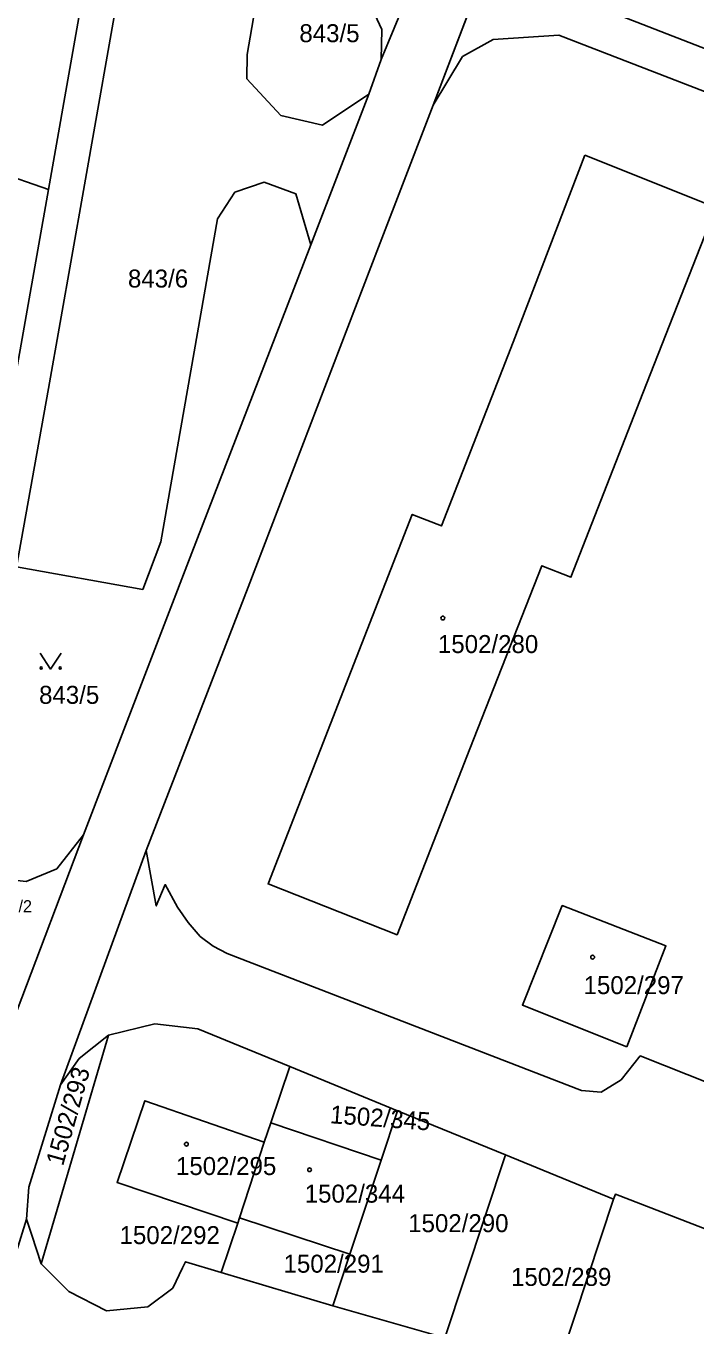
# Model space of a CAD drawing. Extents: x -737240 to -735272, y -1119606 to -1117878.
# Drawn here: x -736841.8 to -736778.5, y -1118698.3 to -1118575.4 of the extents above; entities that cross this region are included whole.
import ezdxf

# ---------------------------------------------------------------- set-up
doc = ezdxf.new("R2010")
doc.units = 0
for name, color, linetype in [('Level 1', 7, 'Continuous'), ('Level 13', 7, 'Continuous'), ('Level 16', 7, 'Continuous'), ('Level 18', 7, 'Continuous'), ('Level 19', 7, 'Continuous'), ('Level 25', 7, 'Continuous')]:
    doc.layers.add(name, color=color, linetype=linetype)

msp = doc.modelspace()

# ---------------------------------------------------------------- linework, layer by layer
at = {"layer": 'Level 1'}
for p, q in [((-736799.83, -1118558.11), (-736808.27, -1118578.61)), ((-736803.36, -1118582.92), (-736794.62, -1118560.04)), ((-736808.27, -1118578.61), (-736809.42, -1118581.87)), ((-736809.42, -1118581.87), (-736814.92, -1118596.1)), ((-736839.7, -1118590.89), (-736858.98, -1118584.15)), ((-736839.7, -1118590.89), (-736842.91, -1118609.08)), ((-736842.68, -1118668.45), (-736836.41, -1118651.87)), ((-736838.58, -1118675.52), (-736830.48, -1118653.36)), ((-736840.39, -1118692.42), (-736834.02, -1118670.81)), ((-736816.91, -1118673.78), (-736818.7, -1118679.12)), ((-736816.91, -1118673.78), (-736806.71, -1118677.96)), ((-736808.27, -1118682.65), (-736806.71, -1118677.96)), ((-736806.71, -1118677.96), (-736796.51, -1118682.14)), ((-736818.7, -1118679.12), (-736819.31, -1118680.92)), ((-736808.27, -1118682.65), (-736818.7, -1118679.12)), ((-736819.31, -1118680.92), (-736821.64, -1118688.08)), ((-736802.24, -1118699.42), (-736796.51, -1118682.14)), ((-736796.51, -1118682.14), (-736786.31, -1118686.32)), ((-736811.21, -1118691.53), (-736808.27, -1118682.65)), ((-736791.58, -1118702.24), (-736786.31, -1118686.32)), ((-736845.46, -1118700.04), (-736841.79, -1118688.22)), ((-736823.37, -1118693.24), (-736821.81, -1118688.6)), ((-736821.81, -1118688.6), (-736821.64, -1118688.08)), ((-736821.64, -1118688.08), (-736811.21, -1118691.53)), ((-736812.83, -1118696.41), (-736811.21, -1118691.53)), ((-736812.83, -1118696.41), (-736823.37, -1118693.24)), ((-736802.24, -1118699.42), (-736812.83, -1118696.41))]:
    msp.add_line(p, q, dxfattribs=at)
for points in [[(-736799.83, -1118558.11), (-736794.62, -1118560.04), (-736803.36, -1118582.92), (-736808.53, -1118596.34), (-736820.83, -1118628.46), (-736830.48, -1118653.36), (-736838.58, -1118675.52), (-736841.55, -1118685.18), (-736841.79, -1118688.22)], [(-736837.93, -1118560.37), (-736835.53, -1118562.25), (-736835.01, -1118564.23), (-736839.7, -1118590.89)], [(-736808.27, -1118578.61), (-736808.19, -1118575.77), (-736809.79, -1118572.37), (-736812.19, -1118570.58), (-736837.93, -1118560.37)], [(-736794.62, -1118560.04), (-736795.14, -1118564.88), (-736794.2, -1118568.06), (-736789.45, -1118572.95), (-736631.53, -1118634.34), (-736618.64, -1118639.21), (-736604.88, -1118644.59), (-736590.23, -1118650.31), (-736570.76, -1118657.53), (-736554.46, -1118664.23), (-736526.71, -1118675.18), (-736508.82, -1118682.05), (-736489.97, -1118689.08), (-736482.05, -1118692.05), (-736473.7, -1118693.54), (-736465.29, -1118693.7), (-736453.8, -1118693.45), (-736428.55, -1118692.43), (-736385.71, -1118690.13)], [(-736809.42, -1118581.87), (-736813.8, -1118584.81), (-736817.74, -1118583.88), (-736820.97, -1118580.42), (-736820.92, -1118578.11), (-736819.89, -1118572.08), (-736832.71, -1118570.04), (-736836.41, -1118590.97), (-736839.69, -1118609.69), (-736842.74, -1118626.55), (-736830.79, -1118628.69), (-736829.09, -1118624.2), (-736823.73, -1118593.67), (-736822.09, -1118591.14), (-736819.33, -1118590.2), (-736816.32, -1118591.29), (-736814.92, -1118596.1)], [(-736679.22, -1118623.96), (-736679.02, -1118622.97), (-736679.11, -1118621.78), (-736679.59, -1118620.8), (-736680.41, -1118619.86), (-736681.28, -1118619.15), (-736682.42, -1118618.5), (-736791.48, -1118576.29), (-736797.67, -1118576.71), (-736800.57, -1118578.32), (-736803.36, -1118582.92)], [(-736830.48, -1118653.36), (-736820.83, -1118628.46), (-736808.53, -1118596.34), (-736803.36, -1118582.92)], [(-736789.02, -1118587.64), (-736795.78, -1118605.3), (-736802.56, -1118622.68), (-736805.33, -1118621.6), (-736812.1, -1118638.96), (-736818.95, -1118656.53), (-736806.76, -1118661.33), (-736799.87, -1118643.75), (-736793.09, -1118626.45), (-736790.33, -1118627.53), (-736783.52, -1118610.13), (-736776.64, -1118592.58), (-736789.02, -1118587.64)], [(-736814.92, -1118596.1), (-736826.31, -1118625.63), (-736836.41, -1118651.87)], [(-736836.41, -1118651.87), (-736838.93, -1118655.09), (-736841.8, -1118656.3), (-736845.47, -1118655.88), (-736850.78, -1118654)], [(-736743.06, -1118693.88), (-736774.57, -1118681.65), (-736775.83, -1118680.53), (-736776.86, -1118678.43), (-736777.06, -1118675.46), (-736783.78, -1118672.78), (-736785.58, -1118675.04), (-736787.46, -1118676.22), (-736789.34, -1118676.05), (-736822.82, -1118663.09), (-736824.14, -1118662.42), (-736825.37, -1118661.48), (-736826.49, -1118660.16), (-736827.5, -1118658.73), (-736828.67, -1118656.59), (-736829.52, -1118658.61), (-736830.48, -1118653.36)], [(-736785.06, -1118671.92), (-736781.36, -1118662.37), (-736791.15, -1118658.57), (-736794.91, -1118667.98), (-736785.06, -1118671.92)], [(-736834.02, -1118670.81), (-736829.66, -1118669.75), (-736825.6, -1118670.22), (-736816.91, -1118673.78)], [(-736838.58, -1118675.52), (-736836.82, -1118673.03), (-736834.02, -1118670.81)], [(-736840.39, -1118692.42), (-736841.29, -1118689.72), (-736841.79, -1118688.22), (-736841.55, -1118685.18), (-736838.58, -1118675.52)], [(-736819.31, -1118680.92), (-736830.6, -1118677.02), (-736833.23, -1118684.76), (-736821.81, -1118688.6)], [(-736786.31, -1118686.32), (-736786.13, -1118685.85), (-736728.39, -1118708.19), (-736726.61, -1118709.13), (-736725.45, -1118710.18), (-736724.78, -1118711.54), (-736724.55, -1118713.09), (-736724.66, -1118714.12), (-736725.19, -1118715.56), (-736726.2, -1118716.77), (-736727.08, -1118717.35), (-736728.03, -1118717.77), (-736729, -1118717.93), (-736730.05, -1118717.92), (-736731.39, -1118717.49)], [(-736841.79, -1118688.22), (-736841.29, -1118689.72), (-736840.39, -1118692.42), (-736837.78, -1118695.06), (-736834.21, -1118696.88), (-736830.31, -1118696.5), (-736827.96, -1118694.72), (-736827.03, -1118692.81), (-736826.75, -1118692.23), (-736823.37, -1118693.24), (-736812.83, -1118696.41), (-736802.24, -1118699.42)], [(-736823.37, -1118693.24), (-736826.75, -1118692.23), (-736827.03, -1118692.81), (-736827.96, -1118694.72), (-736830.31, -1118696.5), (-736834.21, -1118696.88), (-736837.78, -1118695.06), (-736840.39, -1118692.42)]]:
    msp.add_lwpolyline(points, dxfattribs=at)
at = {"layer": 'Level 13'}
for points in [[(-736794.62, -1118560.04), (-736803.36, -1118582.92), (-736808.53, -1118596.34), (-736820.83, -1118628.46), (-736830.48, -1118653.36), (-736838.58, -1118675.52), (-736841.55, -1118685.18), (-736841.79, -1118688.22), (-736841.29, -1118689.72), (-736840.39, -1118692.42), (-736837.78, -1118695.06), (-736834.21, -1118696.88), (-736830.31, -1118696.5), (-736827.96, -1118694.72), (-736827.03, -1118692.81), (-736826.75, -1118692.23), (-736823.37, -1118693.24), (-736812.83, -1118696.41), (-736802.24, -1118699.42)], [(-736794.62, -1118560.04), (-736803.36, -1118582.92), (-736808.53, -1118596.34), (-736820.83, -1118628.46), (-736830.48, -1118653.36), (-736838.58, -1118675.52), (-736841.55, -1118685.18), (-736841.79, -1118688.22), (-736841.29, -1118689.72), (-736840.39, -1118692.42), (-736837.78, -1118695.06), (-736834.21, -1118696.88), (-736830.31, -1118696.5), (-736827.96, -1118694.72)], [(-736827.96, -1118694.72), (-736827.03, -1118692.81), (-736826.75, -1118692.23), (-736823.37, -1118693.24), (-736812.83, -1118696.41), (-736802.24, -1118699.42), (-736791.58, -1118702.24), (-736781.47, -1118704.4), (-736764.69, -1118707.01), (-736754.19, -1118708.64), (-736734.17, -1118711.39), (-736733.93, -1118712.88), (-736733.54, -1118715.27), (-736731.39, -1118717.49), (-736730.96, -1118717.94), (-736726.61, -1118718.57), (-736723.35, -1118716.43), (-736722.58, -1118714.49), (-736673.37, -1118721.44)]]:
    msp.add_lwpolyline(points, dxfattribs=at)
at = {"layer": 'Level 25'}
msp.add_lwpolyline([(-736838.5, -1118634.71), (-736839.5, -1118636.21), (-736840.5, -1118634.71)], dxfattribs=at)
for centre in [(-736840.4, -1118636.11), (-736838.6, -1118636.11)]:
    msp.add_circle(centre, 0.1, dxfattribs=at)
for centre in [(-736802.44, -1118631.39), (-736788.28, -1118663.45), (-736826.67, -1118681.12), (-736815.03, -1118683.54)]:
    msp.add_ellipse(centre, major_axis=(0.18, 0), ratio=0.9848078, dxfattribs=at)

# ---------------------------------------------------------------- texts
at = {"layer": 'Level 16'}
msp.add_text('843/5', height=1.7, dxfattribs=at).set_placement((-736815.995, -1118576.96))
at = {"layer": 'Level 18'}
for s, height, p in [('843/6', 1.7, (-736832.195, -1118600.15)), ('843/5', 1.7, (-736840.595, -1118639.5)), ('277/2', 1.14, (-736845.08, -1118659.2)), ('1502/290', 1.7, (-736805.71, -1118689.44)), ('1502/292', 1.7, (-736832.99, -1118690.57)), ('1502/291', 1.7, (-736817.49, -1118693.27)), ('1502/289', 1.7, (-736795.99, -1118694.52))]:
    msp.add_text(s, height=height, dxfattribs=at).set_placement(p)
for s, rotation, p in [('1502/293', 74.25639, (-736838.337, -1118683.258)), ('1502/345', 355.80897, (-736813.14, -1118679.14))]:
    msp.add_text(s, height=1.7, rotation=rotation, dxfattribs=at).set_placement(p)
at = {"layer": 'Level 19'}
for s, p in [('1502/280', (-736802.9, -1118634.7)), ('1502/297', (-736789.135, -1118666.94)), ('1502/295', (-736827.655, -1118684.04)), ('1502/344', (-736815.49, -1118686.65))]:
    msp.add_text(s, height=1.7, dxfattribs=at).set_placement(p)

doc.saveas('drawing.dxf')
